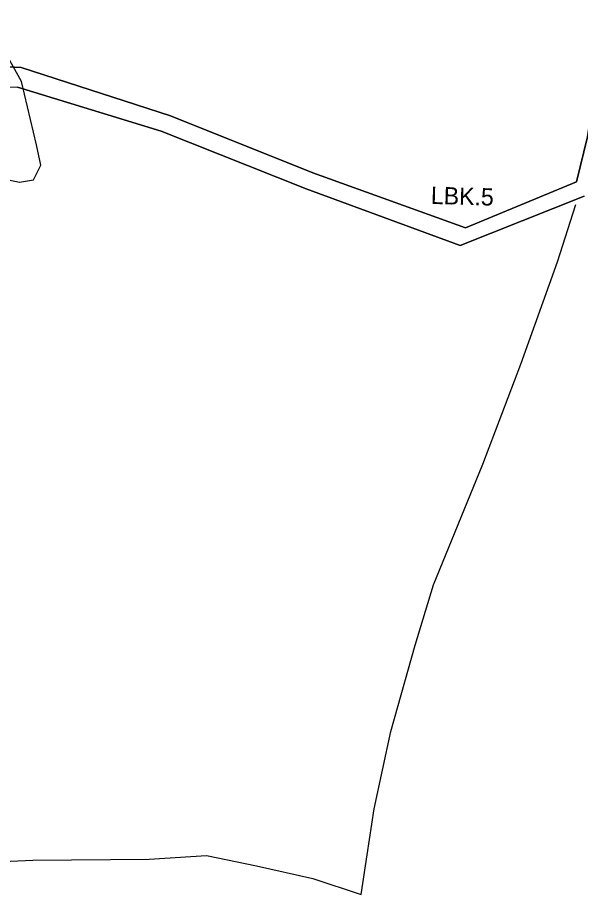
# Model space of a CAD drawing. Extents: x -555426 to -553015, y -1186745 to -1182595.
# Drawn here: x -554710 to -554287, y -1186679 to -1186019 of the extents above; entities that cross this region are included whole.
import ezdxf

# ---------------------------------------------------------------- set-up
doc = ezdxf.new("R2010")
doc.units = 0
for name, color, linetype in [('Level 12', 7, 'Continuous'), ('Level 51', 7, 'Continuous'), ('svahove_deformace', 7, 'Continuous'), ('USES_ID', 7, 'Continuous'), ('USES_LBK_navrh', 7, 'Continuous')]:
    doc.layers.add(name, color=color, linetype=linetype)

msp = doc.modelspace()

# ---------------------------------------------------------------- linework, layer by layer
at = {"layer": 'Level 12'}
for points in [[(-554281.22, -1186109.23), (-554289.52, -1186142.99), (-554373.27, -1186177.71), (-554488.13, -1186136.21), (-554595.17, -1186093.44), (-554707.7, -1186057.02), (-554717.81, -1186056.56)], [(-554719.54, -1186071.5), (-554710.39, -1186071.91), (-554602.25, -1186105.03), (-554493.14, -1186148.4), (-554377.29, -1186191), (-554283.71, -1186153.97)]]:
    msp.add_lwpolyline(points, dxfattribs=at)
at = {"layer": 'Level 51'}
msp.add_lwpolyline([(-554783.35, -1186657.45), (-554698.8, -1186653.52), (-554611.25, -1186652.83), (-554568.05, -1186650.06), (-554530.4, -1186657.91), (-554488.18, -1186667.38), (-554451.68, -1186679.4), (-554447.29, -1186649.48), (-554441.86, -1186615.06), (-554429.39, -1186556.85), (-554411.14, -1186491.7), (-554397.17, -1186446.43), (-554360.09, -1186355.64), (-554331.56, -1186280.22), (-554303.84, -1186203.18), (-554289.98, -1186160.03)], dxfattribs=at)
at = {"layer": 'svahove_deformace'}
msp.add_lwpolyline([(-554692.79, -1186130.61), (-554696.09, -1186115.11), (-554707.43, -1186067.62), (-554726.31, -1186034.06), (-554740.14, -1186025.74), (-554747.99, -1186025.4), (-554759.18, -1186031.7), (-554766.95, -1186052.71), (-554761.79, -1186082.71), (-554742.79, -1186115.49), (-554721.91, -1186140.64), (-554708.85, -1186143.31), (-554698.33, -1186141.67), (-554692.79, -1186130.61)], dxfattribs=at)
at = {"layer": 'USES_LBK_navrh'}
for p, q in [((-554595.17, -1186093.44), (-554488.13, -1186136.21)), ((-554488.13, -1186136.21), (-554373.27, -1186177.71)), ((-554373.27, -1186177.71), (-554289.52, -1186142.99)), ((-554283.71, -1186153.97), (-554377.29, -1186191))]:
    msp.add_line(p, q, dxfattribs=at)
for points in [[(-554289.52, -1186142.99), (-554281.22, -1186109.23), (-554272.29, -1186050.65), (-554265.33, -1186019.41)], [(-554717.81, -1186056.56), (-554707.7, -1186057.02), (-554595.17, -1186093.44)], [(-554377.29, -1186191), (-554493.14, -1186148.4), (-554602.25, -1186105.03), (-554710.39, -1186071.91)]]:
    msp.add_lwpolyline(points, dxfattribs=at)

# ---------------------------------------------------------------- texts
at = {"layer": 'USES_ID'}
msp.add_text('LBK.5', height=13, rotation=358.38567, dxfattribs=at).set_placement((-554399.38, -1186159.68))

doc.saveas('drawing.dxf')
